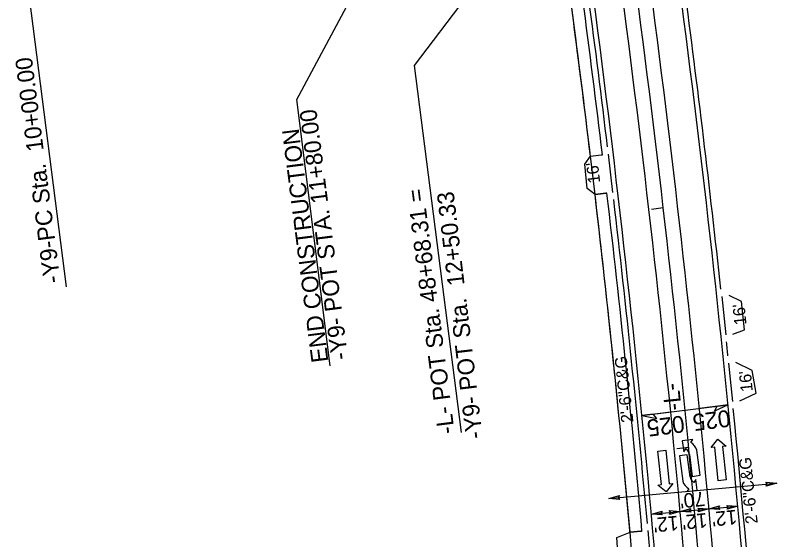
# Model space of a CAD drawing. Extents: x 2367848 to 2369479, y 800728 to 808616.
# Drawn here: x 2368495.3 to 2368811.3, y 804888 to 805105.7 of the extents above; entities that cross this region are included whole.
import ezdxf

# ---------------------------------------------------------------- set-up
doc = ezdxf.new("R2010")
doc.units = 0
for name, color, linetype in [('Prop Conc 2ft 6in Curb and Gutter', 7, 'Continuous'), ('Prop Conc 4in Sidewalk', 7, 'Continuous'), ('Prop Conc Drive Radius Type', 7, 'Continuous'), ('Prop Conc Driveway', 7, 'Continuous'), ('Prop Dimension', 7, 'Continuous'), ('Prop EOT', 7, 'Continuous'), ('Prop Horizontal Alignment', 7, 'Continuous'), ('Prop Horizontal Alignment Station Label', 7, 'Continuous'), ('Prop Horizontal Alignment Tick Small', 7, 'Continuous'), ('Prop Lane Arrow CELL', 7, 'Continuous'), ('Prop Lane Lines', 7, 'Continuous'), ('Prop Shade Light', 7, 'Continuous'), ('Prop Superelevation  Arrow CELL', 7, 'Continuous'), ('Prop Superelevation Label', 7, 'Continuous'), ('Prop Terminator CELL', 7, 'Continuous')]:
    doc.layers.add(name, color=color, linetype=linetype)

msp = doc.modelspace()

# ---------------------------------------------------------------- linework, layer by layer
at = {"layer": 'Prop Conc 2ft 6in Curb and Gutter'}
for radius, start, end in [(5386.57, 6.19237, 7.54241), (5346.57, 6.87586, 7.54241), (5346.57, 5.19262, 6.6401), (5386.57, 5.89645, 5.95836), (5386.57, 3.52424, 5.66244)]:
    msp.add_arc((2363433, 804410.95), radius, start, end, dxfattribs=at)
at = {"layer": 'Prop Conc 4in Sidewalk'}
for centre, radius, start, end in [((2363433, 804410.95), 5344.07, 6.84421, 7.54241), ((2363433, 804410.95), 5339.07, 6.82775, 7.54241), ((2368738.14, 805050.69), 3, 276.7986, 286.4354), ((2363433, 804410.95), 5339.07, 5.15191, 6.69499), ((2368740.72, 805028.83), 3.01, 86.9414, 96.5448), ((2363433, 804410.95), 5344.07, 5.16097, 6.67173), ((2368754.65, 804894.57), 3, 275.0943, 284.7283)]:
    msp.add_arc(centre, radius, start, end, dxfattribs=at)
at = {"layer": 'Prop Conc Drive Radius Type'}
for p, q in [((2368743.36, 805032.17), (2368741.48, 805048.06)), ((2368788.52, 804989.01), (2368790.17, 804973.09)), ((2368791.35, 804961.33), (2368792.99, 804945.42)), ((2368759.31, 804875.92), (2368757.9, 804891.85))]:
    msp.add_line(p, q, dxfattribs=at)
at = {"layer": 'Prop Conc Driveway'}
for p, q in [((2368734.03, 805047.18), (2368738.5, 805047.7)), ((2368735.91, 805031.29), (2368734.03, 805047.18)), ((2368735.91, 805031.29), (2368740.38, 805031.82)), ((2368744.93, 804888.96), (2368750.43, 804891.19)), ((2368754.91, 804891.59), (2368750.43, 804891.19)), ((2368751.84, 804875.25), (2368750.43, 804891.19)), ((2368745.88, 804876.04), (2368744.93, 804888.96))]:
    msp.add_line(p, q, dxfattribs=at)
at = {"layer": 'Prop Dimension'}
for p, q in [((2368612.19, 805070.76), (2368673.07, 805184.37)), ((2368625.96, 804960.17), (2368612.19, 805070.76)), ((2368741.63, 804905.08), (2368811.33, 804911.57)), ((2368759.29, 804898.7), (2368795.14, 804901.95))]:
    msp.add_line(p, q, dxfattribs=at)
at = {"layer": 'Prop EOT'}
for p, q in [((2368731.63, 805043.83), (2368734.03, 805047.18)), ((2368732.62, 805033.8), (2368731.63, 805043.83)), ((2368735.91, 805031.29), (2368732.62, 805033.8)), ((2368796.68, 804986.88), (2368791.51, 804989.32)), ((2368797.9, 804975.07), (2368796.68, 804986.88)), ((2368793.15, 804973.4), (2368797.9, 804975.07)), ((2368801.16, 804958.31), (2368794.33, 804961.64)), ((2368802.77, 804948.88), (2368801.16, 804958.31)), ((2368795.97, 804945.73), (2368802.77, 804948.88))]:
    msp.add_line(p, q, dxfattribs=at)
for radius in [5384.57, 5348.57]:
    msp.add_arc((2363433, 804410.95), radius, 2.79654, 7.54241, dxfattribs=at)
at = {"layer": 'Prop Horizontal Alignment'}
msp.add_arc((2363433, 804410.95), 5366.57, 2.79654, 7.54241, dxfattribs=at)
at = {"layer": 'Prop Horizontal Alignment Station Label'}
for p, q in [((2368661.01, 805084.82), (2368742.91, 805192.66)), ((2368495.99, 805153.65), (2368516.51, 804993.03)), ((2368680.46, 804932.54), (2368661.01, 805084.82))]:
    msp.add_line(p, q, dxfattribs=at)
at = {"layer": 'Prop Horizontal Alignment Tick Small'}
for p, q in [((2368764.25, 805025.71), (2368759.28, 805025.14)), ((2368764.25, 805025.71), (2368759.28, 805025.14)), ((2368774.78, 804926.27), (2368769.8, 804925.79)), ((2368774.78, 804926.27), (2368769.8, 804925.79))]:
    msp.add_line(p, q, dxfattribs=at)
at = {"layer": 'Prop Lane Arrow CELL'}
for p, q in [((2368776.55, 804929.6), (2368772.14, 804929.02)), ((2368772.14, 804929.02), (2368772.72, 804924.56)), ((2368775.65, 804928.37), (2368776.55, 804929.6)), ((2368784.07, 804926.28), (2368786.82, 804929.73)), ((2368786.82, 804929.73), (2368790.33, 804926.93)), ((2368772.72, 804924.56), (2368773.63, 804925.73)), ((2368785.56, 804926.43), (2368784.07, 804926.28)), ((2368787.01, 804912.51), (2368785.56, 804926.43)), ((2368790.33, 804926.93), (2368788.84, 804926.78)), ((2368788.84, 804926.78), (2368790.3, 804912.85)), ((2368762, 804924.82), (2368765.28, 804925.16)), ((2368763.46, 804910.9), (2368762, 804924.82)), ((2368765.28, 804925.16), (2368766.74, 804911.24)), ((2368774.21, 804923.24), (2368770.93, 804922.81)), ((2368770.93, 804922.81), (2368772.31, 804912.35)), ((2368775.4, 804914.17), (2368774.21, 804923.24)), ((2368775.09, 804923.41), (2368776.29, 804914.33)), ((2368779.56, 804914.76), (2368778.18, 804925.22)), ((2368776.29, 804914.33), (2368779.56, 804914.76)), ((2368761.96, 804910.74), (2368763.46, 804910.9)), ((2368765.47, 804907.94), (2368761.96, 804910.74)), ((2368768.23, 804911.4), (2368765.47, 804907.94)), ((2368766.74, 804911.24), (2368768.23, 804911.4)), ((2368777.77, 804913.02), (2368776.87, 804911.84)), ((2368778.31, 804908.55), (2368777.77, 804913.02)), ((2368790.3, 804912.85), (2368787.01, 804912.51)), ((2368774.84, 804909.2), (2368773.94, 804908.02)), ((2368773.94, 804908.02), (2368778.31, 804908.55))]:
    msp.add_line(p, q, dxfattribs=at)
for centre, radius, start, end in [((2368771.83, 804923), 3.27, 7.4915, 57.1497), ((2368773.12, 804923.77), 5.25, 16.1676, 61.4793), ((2368778.63, 804914.58), 3.27, 187.4915, 237.1497), ((2368777.34, 804913.81), 5.25, 196.1676, 241.4793)]:
    msp.add_arc(centre, radius, start, end, dxfattribs=at)
at = {"layer": 'Prop Lane Lines'}
for radius in [5372.57, 5360.57]:
    msp.add_arc((2363433, 804410.95), radius, 2.79654, 7.54241, dxfattribs=at)
at = {"layer": 'Prop Shade Light'}
for p, q in [((2368734.03, 805047.18), (2368738.5, 805047.7)), ((2368740.38, 805031.82), (2368735.91, 805031.29)), ((2368750.43, 804891.19), (2368754.91, 804891.59))]:
    msp.add_line(p, q, dxfattribs=at)
for centre, radius, start, end in [((2363433, 804410.95), 5344.07, 6.84421, 7.54241), ((2363433, 804410.95), 5339.07, 6.84382, 7.54241), ((2368738.14, 805050.69), 3, 276.7986, 286.4354), ((2363433, 804410.95), 5339.07, 5.16061, 6.67212), ((2368740.72, 805028.83), 3.01, 86.9414, 96.5448), ((2363433, 804410.95), 5344.07, 5.16097, 6.67173), ((2368754.65, 804894.57), 3, 275.0943, 284.7283)]:
    msp.add_arc(centre, radius, start, end, dxfattribs=at)
at = {"layer": 'Prop Superelevation  Arrow CELL'}
for p, q in [((2368791.12, 804944.07), (2368779.21, 804942.56)), ((2368755.39, 804939.54), (2368767.3, 804941.05))]:
    msp.add_line(p, q, dxfattribs=at)
for points in [[(2368791.12, 804944.07), (2368785.42, 804941.33), (2368786.53, 804943.48)], [(2368755.39, 804939.54), (2368761.6, 804938.31), (2368759.98, 804940.12)]]:
    msp.add_lwpolyline(points, close=True, dxfattribs=at)
at = {"layer": 'Prop Superelevation Label'}
msp.add_line((2368755.39, 804939.54), (2368791.12, 804944.07), dxfattribs=at)
at = {"layer": 'Prop Terminator CELL'}
for points in [[(2368806.77, 804911.89), (2368811.33, 804911.57), (2368806.91, 804910.32), (2368807.4, 804911.17)], [(2368746.18, 804904.77), (2368741.63, 804905.08), (2368746.05, 804906.34), (2368745.56, 804905.49)], [(2368775.79, 804899.46), (2368771.24, 804899.78), (2368775.66, 804901.03), (2368775.17, 804900.17)], [(2368778.64, 804901.19), (2368783.19, 804900.86), (2368778.77, 804899.62), (2368779.26, 804900.47)], [(2368787.75, 804900.54), (2368783.19, 804900.86), (2368787.61, 804902.11), (2368787.12, 804901.26)], [(2368790.59, 804902.27), (2368795.14, 804901.95), (2368790.72, 804900.7), (2368791.21, 804901.55)], [(2368763.84, 804898.38), (2368759.29, 804898.7), (2368763.71, 804899.95), (2368763.22, 804899.09)], [(2368766.69, 804900.11), (2368771.24, 804899.78), (2368766.82, 804898.54), (2368767.31, 804899.39)]]:
    msp.add_lwpolyline(points, close=True, dxfattribs=at)

# ---------------------------------------------------------------- texts
at = {"layer": 'Prop Dimension'}
for s, height, rotation, p in [('-Y9- POT STA. 11+80.00', 7, 97.2784, (2368633.49, 804963.04)), ('END CONSTRUCTION', 7, 97.2784, (2368625.31, 804962)), ("16'", 5, 96.7344, (2368738.1, 805036.23)), ("16'", 5, 96.0247, (2368798.8, 804977.4)), ('2\'-6"C&G', 5, 95.9554, (2368751.86, 804936.84)), ("16'", 5, 95.7289, (2368801.39, 804949.68)), ('2\'-6"C&G', 5, 95.9554, (2368803.45, 804894.88)), ("70'", 6, 185.8359, (2368781.25, 804908.07)), ("12'", 6, 185.6911, (2368794.53, 804900.52)), ("12'", 6, 185.6911, (2368770.28, 804898.05)), ("12'", 6, 185.6911, (2368782.19, 804899.18))]:
    msp.add_text(s, height=height, rotation=rotation, dxfattribs=at).set_placement(p)
at = {"layer": 'Prop Horizontal Alignment Station Label'}
for s, rotation, p in [('-Y9-PC Sta.  10+00.00', 97.2784, (2368514.17, 804994.93)), ('-L- POT Sta. 48+68.31 =', 97.2784, (2368677.71, 804932.33)), ('-Y9- POT Sta.  12+50.33', 96.7709, (2368689.37, 804930.28)), ('-L-', 95.8713, (2368771.86, 804941.96))]:
    msp.add_text(s, height=7, rotation=rotation, dxfattribs=at).set_placement(p)
at = {"layer": 'Prop Superelevation Label'}
for p in [(2368791.55, 804941.99), (2368772.57, 804939.67)]:
    msp.add_text('025', height=7, rotation=187.2247, dxfattribs=at).set_placement(p)

doc.saveas('drawing.dxf')
